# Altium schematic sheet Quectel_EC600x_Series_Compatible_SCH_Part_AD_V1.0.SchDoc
size A2
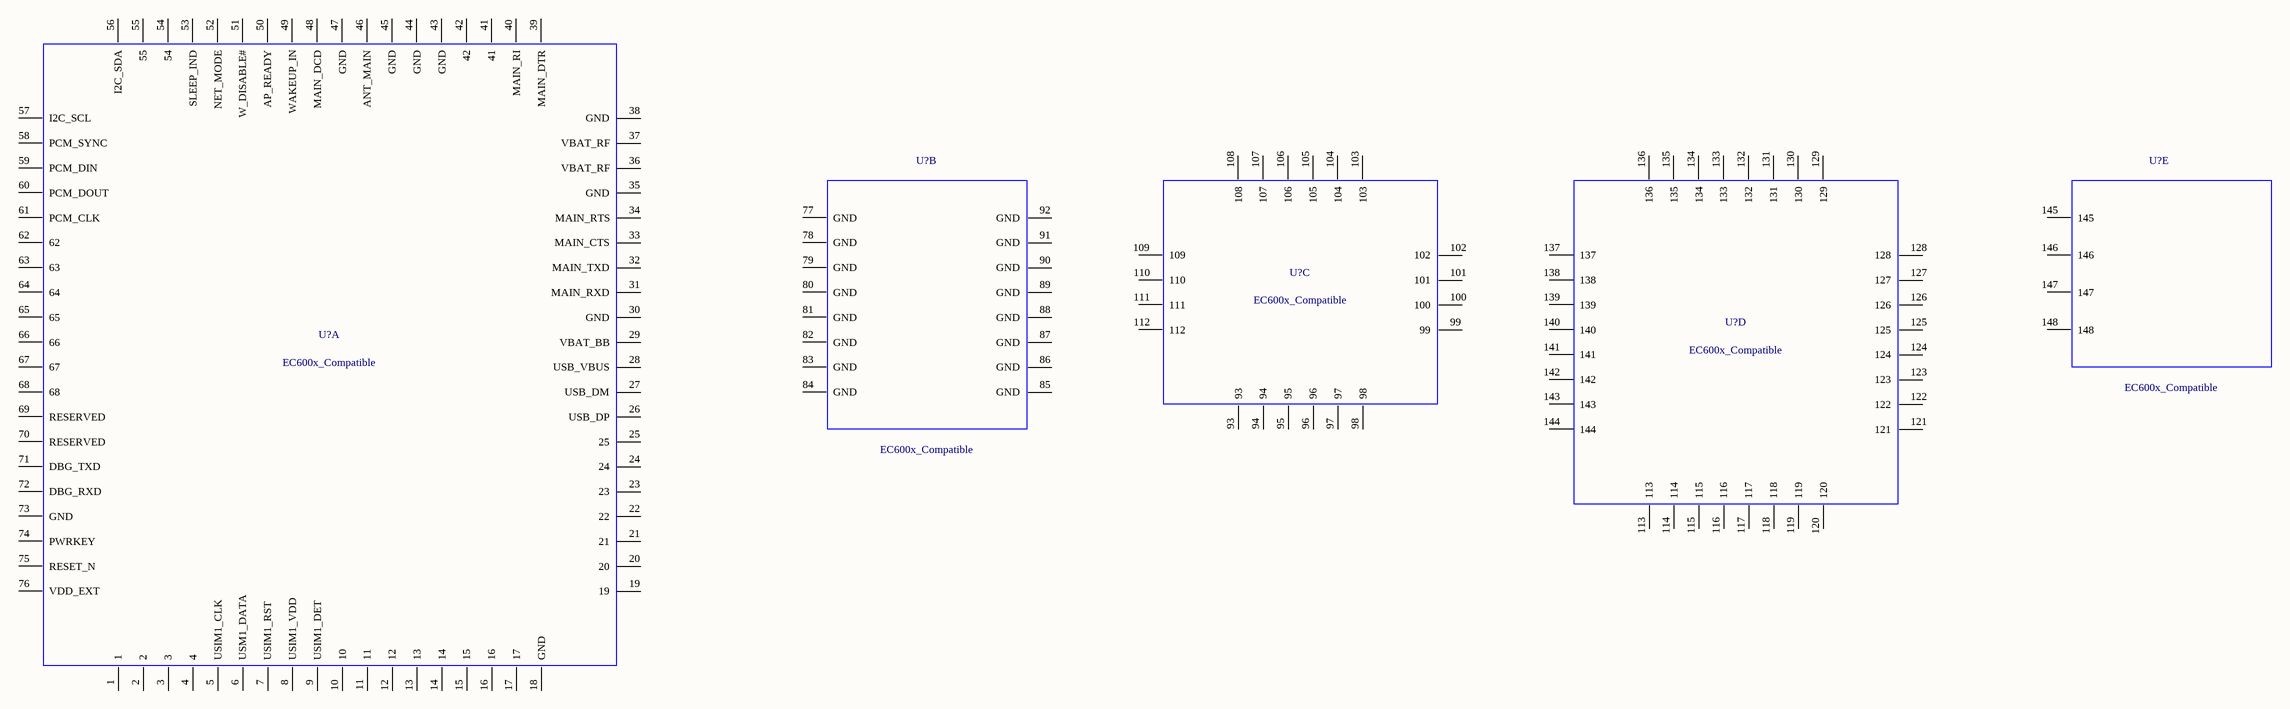
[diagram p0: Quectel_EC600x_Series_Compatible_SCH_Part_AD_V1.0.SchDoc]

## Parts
(Parts that share a designator on the sheet are numbered #1, #2 ... from top to bottom, then left to right.)
U?#1  EC600x_Compatible  (part E of 5)
U?#2  EC600x_Compatible  (part C of 5)
U?#3  EC600x_Compatible  (part B of 5)
U?#4  EC600x_Compatible  (part D of 5)
U?#5  EC600x_Compatible  (part A of 5)

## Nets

Not connected (* = marked no-connect by the designer): U?#1 145 146 147 148; U?#2 93 94 95 96 97 98 99 100 101 102 103 104 105 106 107 108 109 110 111 112; U?#3 77(GND) 78(GND) 79(GND) 80(GND) 81(GND) 82(GND) 83(GND) 84(GND) 85(GND) 86(GND) 87(GND) 88(GND) 89(GND) 90(GND) 91(GND) 92(GND); U?#4 113 114 115 116 117 118 119 120 121 122 123 124 125 126 127 128 129 130 131 132 133 134 135 136 137 138 139 140 141 142 143 144; U?#5 1 2 3 4 5(USIM1_CLK) 6(USM1_DATA) 7(USIM1_RST) 8(USIM1_VDD) 9(USIM1_DET) 10 11 12 13 14 15 16 17 18(GND) 19 20 21 22 23 24 25 26(USB_DP) 27(USB_DM) 28(USB_VBUS) 29(VBAT_BB) 30(GND) 31(MAIN_RXD) 32(MAIN_TXD) 33(MAIN_CTS) 34(MAIN_RTS) 35(GND) 36(VBAT_RF) 37(VBAT_RF) 38(GND) 39(MAIN_DTR) 40(MAIN_RI) 41 42 43(GND) 44(GND) 45(GND) 46(ANT_MAIN) 47(GND) 48(MAIN_DCD) 49(WAKEUP_IN) 50(AP_READY) 51(W_DISABLE#) 52(NET_MODE) 53(SLEEP_IND) 54 55 56(I2C_SDA) 57(I2C_SCL) 58(PCM_SYNC) 59(PCM_DIN) 60(PCM_DOUT) 61(PCM_CLK) 62 63 64 65 66 67 68 69(RESERVED) 70(RESERVED) 71(DBG_TXD) 72(DBG_RXD) 73(GND) 74(PWRKEY) 75(RESET_N) 76(VDD_EXT)

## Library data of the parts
U?#1-U?#5 = EC600x_Compatible: EC600X_Compatible Module LCC76PIN LGA72PIN H2.4mm RO; Manufacturer: Quectel; Geometry.Height: 2.4mm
